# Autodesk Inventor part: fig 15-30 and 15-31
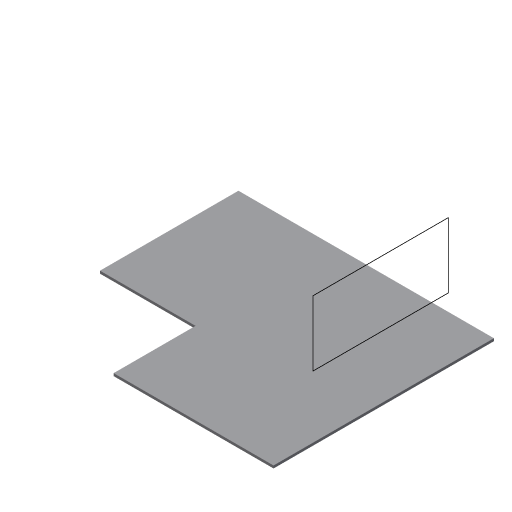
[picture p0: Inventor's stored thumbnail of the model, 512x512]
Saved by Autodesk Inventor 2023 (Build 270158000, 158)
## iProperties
Created: 2005-03
Part Number: fig 15-30 and 15-31
Document SubType Name: Sheet Metal
Designer: CADCIM
Manufacturer: Standard
Standards Organization: Custom
Density: 1 g/cm^3
Sheet Metal Rule: Default
Material: Generic
Appearance: Default
Author: CADCIM
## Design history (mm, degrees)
node "Face1"
  sketch "Sketch1"
    geometry: L1 (29.25, 32.25)-(-19.875, 32.25); L2 (-19.875, 32.25)-(-19.875, 5.625); L3 (-19.875, 5.625)-(-1.5, 5.625); L4 (-1.5, 5.625)-(-1.5, -10.125); L5 (-1.5, -10.125)-(29.25, -10.125); L6 (29.25, -10.125)-(29.25, 32.25)
    constraints: 12 end point, 4 parallel, 1 horizontal, 1 perpendicular
sketch "Sketch2"
  geometry: L1 (-12.475, 7.526)-(-25.013, 7.526); L2 (-25.013, 7.526)-(-25.013, 33.56); L3 (-25.013, 33.56)-(-12.475, 33.56); L4 (-12.475, 33.56)-(-12.475, 7.526)
  constraints: 8 end point, 2 parallel, 1 horizontal, 1 perpendicular
body "Solid1"
face "Plate1" dims "d1" = 0.5 (= Thickness)
other parameters: "Thickness" = 0.5, "BendRadius" = 0.5 (= Thickness), "BendReliefWidth" = 0.5 (= Thickness), "BendReliefDepth" = 0.25 (= 0.5 x Thickness), "CornerReliefSize" = 2 (= 4 x Thickness), "SeamGap" = 0.01, "MinimumRemnant" = 1 (= 2 x Thickness), "TransitionRadius" = 0.5 (= BendRadius), "d0" = 0.5 (= BendRadius), "JacobiRadiusSize" = 0.5 (= Thickness), "GapSize" = 0.5 (= Thickness)
